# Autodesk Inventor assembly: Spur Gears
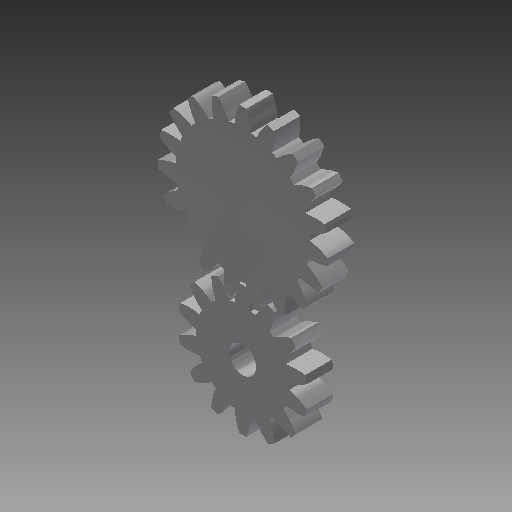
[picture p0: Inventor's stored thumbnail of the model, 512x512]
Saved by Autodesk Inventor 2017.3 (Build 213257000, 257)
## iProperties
ClientObjectVersion: 1
Created: 2020-03
Part Number: Spur Gears
Document SubType Name: Assembly
Designer: Tim_G
Categories: <?xml version="1.0" encoding="UTF-16"?> <MemberInstance><Categories><FamilyTemplate/><ParamToTemplateMap><ParamToTemplate><ParamToTemplate CategoryParameter="//
Author: Tim_G
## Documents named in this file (3)
- C:\Users\Tim_G\OneDrive - McMaster University\Documents\Documents\Books\McMaster First Year Courses\Winter Engineering 1C03\Project\Project Files (Prosthetic Frame Assembly)\Hand Assembly\Design Accelerator\Spur Gears6.iam
- C:\Users\Tim_G\OneDrive - McMaster University\Documents\Documents\Books\McMaster First Year Courses\Winter Engineering 1C03\Project\Project Files (Prosthetic Frame Assembly)\Hand Assembly\Design Accelerator\Spur Gear16.ipt
- C:\Users\Tim_G\OneDrive - McMaster University\Documents\Documents\Books\McMaster First Year Courses\Winter Engineering 1C03\Project\Project Files (Prosthetic Frame Assembly)\Hand Assembly\Design Accelerator\Spur Gear26.ipt
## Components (2 placed, 2 different names)
1. Spur Gear1:1 — Rotation:1
2. Spur Gear2:1 — Rotation:1
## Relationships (1: RelateRotation 1)
- Rotation:1 [RelateRotation]: Spur Gear1:1 ↔ Spur Gear2:1
